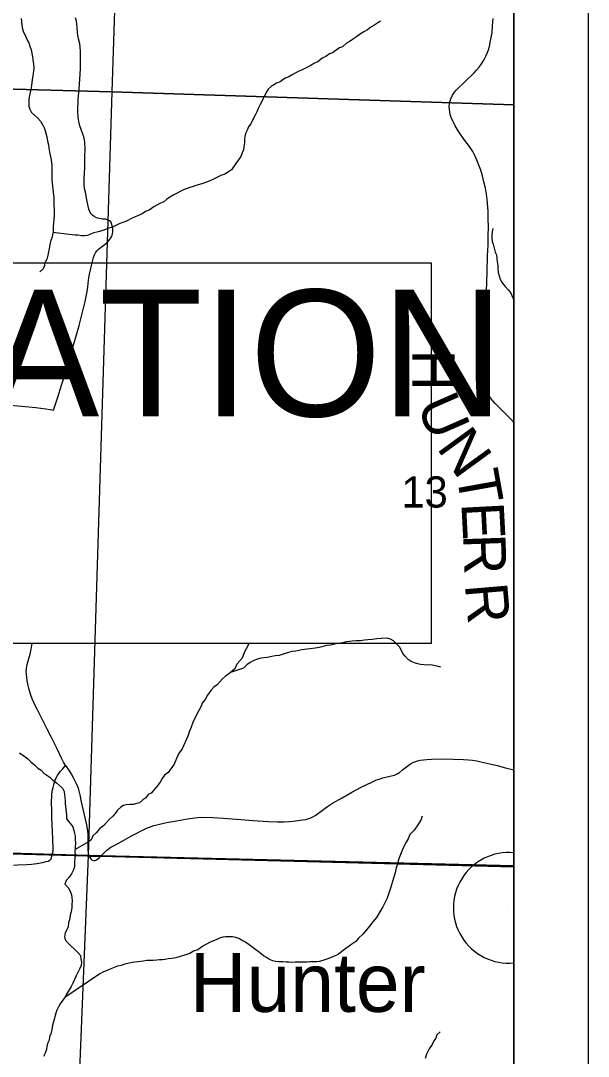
# Model space of a CAD drawing. Extents: x -7.9 to 76.1, y 0 to 22.
# Drawn here: x 8.238 to 9, y 17.882 to 19.274 of the extents above; entities that cross this region are included whole.
import ezdxf

# ---------------------------------------------------------------- set-up
doc = ezdxf.new("R2010")
doc.units = 0
for name, color, linetype in [('DV_X_Township_Line', 7, 'Continuous'), ('GM_X_Corporation_Text', 7, 'Continuous'), ('GM_X_County_Road', 7, 'Continuous'), ('GM_X_County_Road_Text', 7, 'Continuous'), ('GM_X_Minor_River', 7, 'Continuous'), ('GM_X_Section', 7, 'Continuous'), ('GM_X_Section_Text', 7, 'Continuous'), ('GM_X_Township_Road', 7, 'Continuous'), ('GM_X_Unincorporated_Location', 7, 'Continuous'), ('GM_X_Unincorporated_Text', 7, 'Continuous'), ('SC_Scratch1', 7, 'Continuous'), ('SH_Data', 7, 'Continuous'), ('SH_Text', 7, 'Continuous')]:
    doc.layers.add(name, color=color, linetype=linetype)

msp = doc.modelspace()

# ---------------------------------------------------------------- linework, layer by layer
at = {"layer": 'DV_X_Township_Line'}
msp.add_lwpolyline([(5.4916, 20.9), (5.4589, 19.5934), (5.4537, 19.3537), (5.4527, 19.3121), (5.4518, 19.2705), (5.4514, 19.2515), (5.451, 19.2324), (5.4237, 18.2356), (6.0503, 18.2178), (7.6352, 18.1705), (8.1733, 18.1556), (8.2754, 18.1527), (8.3264, 18.1514), (8.3292, 18.1513), (8.3352, 18.1512), (8.3434, 18.151), (8.9, 18.1366), (8.9, 18.1366)], dxfattribs=at)
at = {"layer": 'GM_X_Corporation_Text'}
msp.add_line((8.9, 18.0076), (8.9, 18.1558), dxfattribs=at)
msp.add_arc((8.8933, 18.0817), 0.0744, 84.8505, 275.1495, dxfattribs=at)
at = {"layer": 'GM_X_County_Road'}
msp.add_lwpolyline([(8.9, 18.7338), (8.8999, 18.7339), (8.8956, 18.7388), (8.8898, 18.7447), (8.8814, 18.7529), (8.8749, 18.7593), (8.8716, 18.763), (8.8687, 18.767), (8.8665, 18.7707), (8.8646, 18.7744), (8.8634, 18.7777), (8.8624, 18.7815), (8.8617, 18.7852), (8.8613, 18.7891), (8.8609, 18.796), (8.861, 18.8068), (8.8617, 18.8239), (8.8623, 18.8407), (8.8626, 18.8587), (8.8627, 18.8808), (8.863, 18.8956), (8.8633, 18.9096), (8.8637, 18.9229), (8.8641, 18.9362), (8.8647, 18.9576), (8.8654, 18.972), (8.8657, 18.9852), (8.866, 18.9959), (8.8657, 19.0077), (8.8655, 19.017), (8.8651, 19.0231), (8.864, 19.0335), (8.8631, 19.0406), (8.8619, 19.0484), (8.8599, 19.0572), (8.858, 19.0653), (8.8555, 19.0726), (8.8532, 19.0794), (8.8502, 19.0862), (8.8475, 19.0923), (8.8448, 19.0976), (8.8403, 19.1045), (8.8329, 19.1146), (8.8272, 19.1228), (8.8239, 19.128), (8.8214, 19.1323), (8.8188, 19.1371), (8.8165, 19.1422), (8.8147, 19.1474), (8.8139, 19.151), (8.8136, 19.1537), (8.8133, 19.1586), (8.8135, 19.1616), (8.8143, 19.1652), (8.8158, 19.1694), (8.8176, 19.1733), (8.8204, 19.1774), (8.8227, 19.1802), (8.8348, 19.192), (8.8467, 19.2035), (8.85, 19.207), (8.8533, 19.211), (8.8566, 19.2155), (8.859, 19.2193), (8.8607, 19.2224), (8.8623, 19.226), (8.8641, 19.2299), (8.866, 19.2345), (8.8673, 19.239), (8.8684, 19.2442), (8.8697, 19.2511), (8.8708, 19.2576), (8.8715, 19.2668), (8.8724, 19.2767)], dxfattribs=at)
at = {"layer": 'GM_X_Minor_River'}
for points in [[(8.2383, 19.2766), (8.2392, 19.2678), (8.2396, 19.2641), (8.2416, 19.258), (8.2447, 19.2524), (8.2466, 19.2475), (8.2486, 19.2437), (8.2502, 19.2392), (8.2517, 19.2346), (8.2538, 19.2252), (8.2542, 19.2214), (8.255, 19.2153), (8.2555, 19.2104), (8.2548, 19.2062), (8.2541, 19.199), (8.2534, 19.1944), (8.2527, 19.1906), (8.2524, 19.1864), (8.2513, 19.1811), (8.2506, 19.1773), (8.2495, 19.1731), (8.2489, 19.1682), (8.2485, 19.1636), (8.2486, 19.1587), (8.2502, 19.1545), (8.2525, 19.15), (8.261, 19.1425), (8.2644, 19.1384), (8.2679, 19.1324), (8.2699, 19.1286), (8.2715, 19.1226), (8.2727, 19.1176), (8.2739, 19.1116), (8.2751, 19.1067), (8.2755, 19.1021), (8.2764, 19.0968), (8.2784, 19.0889), (8.2792, 19.0832), (8.2796, 19.079), (8.2797, 19.0737), (8.2794, 19.0661), (8.2795, 19.0597), (8.2799, 19.0559), (8.2804, 19.051), (8.2808, 19.0472), (8.2816, 19.043), (8.2825, 19.0354), (8.2822, 19.0297), (8.2823, 19.0248), (8.2827, 19.021), (8.2828, 19.0161), (8.2828, 19.0123), (8.2821, 19.0066), (8.2815, 18.9971), (8.2812, 18.9899), (8.2798, 18.9819), (8.278, 18.9769), (8.2769, 18.9723), (8.2762, 18.9674), (8.2751, 18.9632), (8.2741, 18.9586), (8.273, 18.9533), (8.2704, 18.9483), (8.2697, 18.9445), (8.2679, 18.94), (8.2637, 18.9361)], [(8.721, 19.2728), (8.7173, 19.2708), (8.712, 19.2669), (8.7079, 19.265), (8.7037, 19.2615), (8.6985, 19.2588), (8.6943, 19.2561), (8.6887, 19.2518), (8.6846, 19.2491), (8.6804, 19.246), (8.6755, 19.2433), (8.6699, 19.2386), (8.6661, 19.2371), (8.6613, 19.234), (8.6564, 19.2305), (8.6526, 19.2289), (8.6477, 19.2254), (8.6428, 19.2231), (8.6368, 19.2184), (8.6323, 19.2165), (8.6263, 19.213), (8.615, 19.2071), (8.6105, 19.2052), (8.6063, 19.2032), (8.6022, 19.2009), (8.5977, 19.1981), (8.5928, 19.1962), (8.5864, 19.1915), (8.5815, 19.1896), (8.5777, 19.1876), (8.574, 19.1853), (8.5702, 19.1814), (8.5676, 19.1772), (8.5617, 19.165), (8.5595, 19.1608), (8.5569, 19.1554), (8.5551, 19.1509), (8.5525, 19.1466), (8.5488, 19.139), (8.547, 19.1348), (8.5436, 19.131), (8.5418, 19.1267), (8.5403, 19.1229), (8.5388, 19.118), (8.5385, 19.1142), (8.5382, 19.1096), (8.5375, 19.1043), (8.5368, 19.1001), (8.5353, 19.0959), (8.5335, 19.0913), (8.5302, 19.0867), (8.5268, 19.0818), (8.5209, 19.0733), (8.5156, 19.0695), (8.5118, 19.0675), (8.5066, 19.0655), (8.496, 19.0601), (8.4907, 19.0581), (8.4824, 19.0549), (8.4779, 19.0534), (8.473, 19.0521), (8.4692, 19.0506), (8.4647, 19.0494), (8.4564, 19.0462), (8.4519, 19.0439), (8.4477, 19.0419), (8.4436, 19.0396), (8.4391, 19.0369), (8.4342, 19.0338), (8.4301, 19.0303), (8.4248, 19.0279), (8.4165, 19.0233), (8.4105, 19.019), (8.4056, 19.017), (8.4011, 19.0143), (8.3958, 19.012), (8.3917, 19.01), (8.3864, 19.0077), (8.38, 19.0042), (8.3751, 19.0026), (8.3709, 19.001), (8.3657, 18.9983), (8.36, 18.9959), (8.3558, 18.9947), (8.3517, 18.9931), (8.3479, 18.9916), (8.3438, 18.9904), (8.34, 18.9895), (8.3362, 18.9884), (8.3317, 18.9868), (8.3275, 18.9848), (8.3234, 18.9844), (8.3196, 18.9843), (8.3146, 18.9854), (8.3109, 18.9853), (8.3071, 18.9857), (8.3029, 18.9864), (8.2811, 18.9892)], [(8.8719, 18.9944), (8.8708, 18.9898), (8.8705, 18.986), (8.8706, 18.9819), (8.871, 18.9769), (8.8722, 18.9732), (8.875, 18.9626), (8.8766, 18.9588), (8.8774, 18.9539), (8.8778, 18.9497), (8.8786, 18.9448), (8.8787, 18.9406), (8.8792, 18.9353), (8.8804, 18.9308), (8.8815, 18.9262), (8.8843, 18.9213), (8.8885, 18.9164), (8.8924, 18.9119), (8.8954, 18.9082), (8.8974, 18.9044), (8.899, 18.9003), (8.9, 18.8979)], [(8.5443, 18.4369), (8.5421, 18.4317), (8.5384, 18.4256), (8.5351, 18.4172), (8.528, 18.4091), (8.5254, 18.4026), (8.5217, 18.3995), (8.5175, 18.3961), (8.5127, 18.3929), (8.5089, 18.3895), (8.5018, 18.3814), (8.4973, 18.3783), (8.4932, 18.3737), (8.4887, 18.3676), (8.4854, 18.3614), (8.4817, 18.3568), (8.4802, 18.3526), (8.4769, 18.3469), (8.4713, 18.3354), (8.4688, 18.3308), (8.4666, 18.3243), (8.4644, 18.319), (8.4622, 18.3125), (8.4548, 18.2953), (8.4496, 18.2884), (8.447, 18.2823), (8.4437, 18.2747), (8.4359, 18.2635), (8.4307, 18.26), (8.4277, 18.2554), (8.4251, 18.2505), (8.4206, 18.2447), (8.4128, 18.2359)], [(8.8022, 18.405), (8.7969, 18.4064), (8.7927, 18.4071), (8.7881, 18.4082), (8.7836, 18.4078), (8.7794, 18.4081), (8.7748, 18.4088), (8.771, 18.4095), (8.7665, 18.4109), (8.7623, 18.4128), (8.7581, 18.4154), (8.7542, 18.4199), (8.7511, 18.4236), (8.7488, 18.4285), (8.7464, 18.4323), (8.743, 18.436), (8.7384, 18.4405), (8.7346, 18.4428), (8.73, 18.4438), (8.722, 18.4437), (8.716, 18.4433), (8.7099, 18.442), (8.7039, 18.4416), (8.6993, 18.4411), (8.694, 18.4403), (8.6883, 18.4402), (8.683, 18.4398), (8.6792, 18.4397), (8.6747, 18.4389), (8.6698, 18.4377), (8.6652, 18.4369), (8.6615, 18.4364), (8.6539, 18.4348), (8.6486, 18.434), (8.6422, 18.4324), (8.6384, 18.4315), (8.6331, 18.4307), (8.6267, 18.4295), (8.6225, 18.429), (8.6153, 18.4282), (8.6111, 18.4274), (8.6074, 18.4265), (8.6021, 18.4261), (8.596, 18.4241), (8.5915, 18.4229), (8.5847, 18.4209), (8.5794, 18.4201), (8.5749, 18.4193), (8.5688, 18.418), (8.5601, 18.4171), (8.5556, 18.4159), (8.551, 18.414), (8.5461, 18.4113), (8.5416, 18.4082), (8.5368, 18.4039), (8.5195, 18.3977)], [(8.2361, 18.29), (8.2419, 18.2859), (8.2472, 18.2818), (8.2514, 18.278), (8.2561, 18.2736), (8.2607, 18.2694), (8.2653, 18.2665), (8.2687, 18.2627), (8.2729, 18.2601), (8.2768, 18.2571), (8.281, 18.2534), (8.286, 18.2497), (8.2898, 18.2459), (8.294, 18.2426), (8.296, 18.238), (8.2968, 18.2335), (8.2972, 18.2297), (8.2973, 18.2255), (8.2977, 18.2217), (8.2978, 18.2179), (8.2982, 18.2141), (8.2991, 18.2062), (8.2995, 18.2016), (8.3018, 18.1979), (8.3053, 18.1941), (8.308, 18.1904), (8.3092, 18.1858), (8.31, 18.1817), (8.3108, 18.1779), (8.3109, 18.1737), (8.3113, 18.1684), (8.311, 18.1631), (8.3107, 18.157), (8.3108, 18.1528), (8.3105, 18.1479), (8.3102, 18.1433), (8.3099, 18.1372), (8.3088, 18.1327), (8.3058, 18.1273), (8.3029, 18.1231), (8.2987, 18.1185), (8.2969, 18.1135), (8.3015, 18.109), (8.3043, 18.1041), (8.3062, 18.0992), (8.3063, 18.0954), (8.3067, 18.0909), (8.3064, 18.0859), (8.3065, 18.0821), (8.3054, 18.0764), (8.3043, 18.0718), (8.3033, 18.0657), (8.3022, 18.0619), (8.3015, 18.0562), (8.2997, 18.052), (8.2974, 18.0482), (8.2964, 18.0429), (8.2976, 18.0387), (8.301, 18.0346), (8.3145, 18.0215), (8.3179, 18.0177), (8.3184, 18.0132), (8.3196, 18.0086), (8.3189, 18.0041), (8.3174, 18.0002), (8.3148, 17.9957), (8.3123, 17.9903), (8.3078, 17.9804), (8.3056, 17.9762), (8.303, 17.9716), (8.3001, 17.967), (8.2971, 17.9612)], [(8.4128, 18.2359), (8.409, 18.2339), (8.4057, 18.2293), (8.4019, 18.227), (8.3974, 18.2227), (8.3936, 18.2219), (8.3887, 18.2207), (8.3849, 18.2207), (8.3796, 18.2202), (8.3759, 18.219), (8.3721, 18.2171), (8.368, 18.2128), (8.3646, 18.2086), (8.3613, 18.2048), (8.3564, 18.2005), (8.3493, 18.1925), (8.3441, 18.1882), (8.3392, 18.1824), (8.3347, 18.1782), (8.3325, 18.1729), (8.3287, 18.1705), (8.3109, 18.1601)], [(8.7769, 18.2049), (8.775, 18.1996), (8.7713, 18.1934), (8.7661, 18.1861), (8.7605, 18.18), (8.7579, 18.1746), (8.7553, 18.1697), (8.7513, 18.1624), (8.7461, 18.149), (8.7447, 18.1448), (8.744, 18.141), (8.7422, 18.1353), (8.7407, 18.1288), (8.7386, 18.1216), (8.7346, 18.1082), (8.7327, 18.1029), (8.7298, 18.0945), (8.7272, 18.0891), (8.7239, 18.083), (8.7202, 18.0765), (8.7154, 18.0688), (8.7105, 18.0627), (8.7061, 18.0569), (8.702, 18.0523), (8.6971, 18.0462), (8.6915, 18.0408), (8.6878, 18.0366), (8.6825, 18.0327), (8.6788, 18.03), (8.6746, 18.0269), (8.6634, 18.0187), (8.6588, 18.0168), (8.654, 18.0144), (8.6475, 18.0125), (8.6434, 18.0109), (8.6388, 18.0097), (8.6351, 18.0092), (8.626, 18.0091), (8.6222, 18.0087), (8.618, 18.0086), (8.6142, 18.0086), (8.61, 18.0089), (8.6062, 18.0088), (8.6021, 18.0084), (8.5979, 18.0087), (8.5941, 18.0087), (8.5899, 18.009), (8.5846, 18.0093), (8.5801, 18.0096), (8.5763, 18.0103), (8.5721, 18.0122), (8.5679, 18.0148), (8.564, 18.017), (8.5583, 18.0218), (8.5518, 18.0267), (8.5464, 18.0308), (8.5395, 18.0356), (8.5353, 18.0378), (8.5307, 18.0404), (8.5269, 18.0419), (8.5224, 18.0426), (8.5174, 18.0429), (8.5129, 18.0428), (8.5091, 18.0424), (8.5049, 18.0408), (8.5004, 18.0389), (8.4967, 18.0373), (8.4914, 18.035), (8.4823, 18.0303), (8.4756, 18.0252), (8.4699, 18.0233), (8.465, 18.0205), (8.4609, 18.019), (8.4564, 18.0178), (8.4518, 18.0162), (8.4462, 18.0146), (8.4409, 18.0137), (8.4359, 18.0133), (8.4318, 18.0125), (8.428, 18.012), (8.4242, 18.012), (8.4204, 18.0116), (8.4159, 18.0111), (8.4121, 18.0111), (8.4068, 18.011), (8.4026, 18.0102), (8.3875, 18.0084), (8.3776, 18.006), (8.3727, 18.0044), (8.3678, 18.0032), (8.3633, 18.0016), (8.3588, 17.9997), (8.3546, 17.9981), (8.349, 17.9957), (8.3441, 17.993), (8.2971, 17.9612)], [(8.2971, 17.9612), (8.2938, 17.957), (8.2908, 17.9528), (8.2886, 17.9486), (8.2863, 17.944), (8.2849, 17.9402), (8.282, 17.9287), (8.2806, 17.9242), (8.2795, 17.9184), (8.2781, 17.9124), (8.2766, 17.9082), (8.2759, 17.904), (8.2744, 17.9001), (8.273, 17.896), (8.2723, 17.8914), (8.2705, 17.8864), (8.2682, 17.8818)], [(8.8009, 17.9151), (8.7968, 17.9109), (8.7953, 17.9067), (8.7924, 17.9028), (8.7905, 17.8979), (8.7864, 17.8921), (8.7827, 17.8852), (8.7809, 17.8791)]]:
    msp.add_lwpolyline(points, dxfattribs=at)
at = {"layer": 'GM_X_Section'}
for points in [[(7.3774, 20.223), (8.3939, 20.1994), (8.3601, 19.1779), (7.3421, 19.2056)], [(7.3421, 19.2056), (8.3601, 19.1779), (8.3283, 18.1522), (7.3083, 18.1826)], [(7.3083, 18.1826), (8.3283, 18.1522), (8.2894, 17.1874), (7.2713, 17.2194)]]:
    msp.add_lwpolyline(points, close=True, dxfattribs=at)
at = {"layer": 'GM_X_Township_Road'}
for points in [[(8.2818, 18.7502), (8.2846, 18.7583), (8.2877, 18.7676), (8.2928, 18.7838), (8.2982, 18.8008), (8.3013, 18.8119), (8.3048, 18.8242), (8.3082, 18.8361), (8.3125, 18.8513), (8.3161, 18.8641), (8.3193, 18.8764), (8.3242, 18.8964), (8.3272, 18.9097), (8.3281, 18.9154), (8.3286, 18.9208), (8.3293, 18.928), (8.3302, 18.933), (8.3314, 18.9386), (8.3329, 18.9447), (8.3356, 18.9553), (8.3369, 18.9591), (8.3382, 18.9616), (8.3402, 18.9643), (8.3423, 18.9665), (8.3495, 18.9718), (8.3538, 18.9754), (8.3567, 18.9788), (8.3589, 18.9819), (8.3597, 18.9834), (8.3605, 18.9853), (8.3611, 18.9872), (8.3614, 18.9897), (8.3613, 18.994), (8.3607, 18.9978), (8.3599, 19.0009), (8.3587, 19.0033), (8.357, 19.0048), (8.3543, 19.006), (8.3517, 19.0067), (8.3471, 19.0071), (8.343, 19.0077), (8.3397, 19.0088), (8.3364, 19.0103), (8.3343, 19.0122), (8.3324, 19.0142), (8.3311, 19.016), (8.3301, 19.0181), (8.3292, 19.0205), (8.3283, 19.0243), (8.3265, 19.0331), (8.3246, 19.043), (8.3236, 19.0482), (8.323, 19.0526), (8.3228, 19.0584), (8.3229, 19.062), (8.3235, 19.0685), (8.3239, 19.0763), (8.3241, 19.0906), (8.3242, 19.1015), (8.324, 19.1104), (8.3235, 19.1133), (8.3224, 19.1175), (8.3213, 19.1209), (8.3189, 19.1274), (8.3173, 19.1323), (8.3159, 19.1382), (8.315, 19.1437), (8.3145, 19.1526), (8.3149, 19.1676), (8.3161, 19.1821), (8.3172, 19.1952), (8.3179, 19.2091), (8.3182, 19.2187), (8.3183, 19.2259), (8.318, 19.2322), (8.3175, 19.2385), (8.317, 19.2423), (8.3155, 19.249), (8.3142, 19.2571), (8.3135, 19.2649), (8.313, 19.2693), (8.3126, 19.2728), (8.3115, 19.2772)], [(8.2243, 18.7568), (8.2388, 18.7558), (8.2583, 18.754), (8.2715, 18.7522), (8.2775, 18.7511), (8.2818, 18.7502)], [(8.2981, 18.2729), (8.2954, 18.2773), (8.2925, 18.2827), (8.2867, 18.2952), (8.2788, 18.3114), (8.2733, 18.3217), (8.2674, 18.3334), (8.2601, 18.3484), (8.2578, 18.3528), (8.2555, 18.3576), (8.2534, 18.3625), (8.2516, 18.3674), (8.2492, 18.3748), (8.2473, 18.3825), (8.2464, 18.3867), (8.2458, 18.391), (8.2454, 18.3955), (8.2453, 18.3994), (8.2457, 18.4032), (8.2466, 18.4085), (8.2481, 18.415), (8.2503, 18.4226), (8.2518, 18.4292), (8.2528, 18.4348), (8.2531, 18.4369)], [(8.3528, 18.1585), (8.3536, 18.1591), (8.3552, 18.1606), (8.3587, 18.1631), (8.3659, 18.167), (8.3773, 18.1732), (8.3867, 18.1783), (8.3946, 18.1825), (8.3988, 18.1848), (8.4026, 18.1866), (8.4069, 18.1886), (8.4108, 18.1901), (8.4164, 18.1921), (8.4205, 18.1934), (8.4337, 18.1962), (8.4471, 18.1984), (8.4618, 18.2013), (8.4717, 18.2027), (8.48, 18.2035), (8.4961, 18.2032), (8.51, 18.2022), (8.5334, 18.2003), (8.5495, 18.1991), (8.5706, 18.1976), (8.5826, 18.1972), (8.5916, 18.1974), (8.5984, 18.1978), (8.6035, 18.1982), (8.6161, 18.1997), (8.6202, 18.2004), (8.6233, 18.2012), (8.6272, 18.2025), (8.6301, 18.2038), (8.6341, 18.2063), (8.6377, 18.2088), (8.6465, 18.2156), (8.6498, 18.2179), (8.6565, 18.2223), (8.6694, 18.2296), (8.6833, 18.2374), (8.6949, 18.2437), (8.7095, 18.2507), (8.7147, 18.2531), (8.717, 18.254), (8.7204, 18.2552), (8.7242, 18.2563), (8.7374, 18.2593), (8.7399, 18.2601), (8.7415, 18.2608), (8.7441, 18.2621), (8.7464, 18.2636), (8.7507, 18.2669), (8.7614, 18.275), (8.7642, 18.2768), (8.767, 18.278), (8.7705, 18.2791), (8.7743, 18.28), (8.7785, 18.2806), (8.7832, 18.281), (8.7895, 18.2813), (8.8025, 18.2818), (8.8191, 18.2814), (8.8325, 18.281), (8.8391, 18.2807), (8.8443, 18.2802), (8.8503, 18.279), (8.8555, 18.2779), (8.8678, 18.275), (8.8775, 18.2727), (8.8888, 18.27), (8.9, 18.2673)], [(8.2816, 18.1614), (8.2809, 18.1744), (8.2804, 18.1843), (8.2796, 18.2032), (8.2794, 18.2127), (8.2791, 18.2229), (8.2795, 18.2333), (8.2802, 18.2385), (8.2812, 18.2434), (8.2827, 18.2489), (8.2842, 18.2533), (8.2856, 18.2564), (8.2873, 18.2597), (8.2889, 18.2623), (8.2908, 18.2647), (8.2939, 18.2682), (8.2981, 18.2729), (8.303, 18.2659), (8.3061, 18.261), (8.3084, 18.2569), (8.3107, 18.2525), (8.3133, 18.2468), (8.3148, 18.2423), (8.317, 18.2335), (8.3192, 18.2239), (8.3214, 18.2142), (8.326, 18.1932), (8.3276, 18.1847), (8.3279, 18.1804), (8.3281, 18.1598)], [(8.2281, 18.1392), (8.234, 18.1393), (8.2462, 18.1397), (8.2524, 18.1402), (8.2593, 18.1412), (8.267, 18.1426), (8.2722, 18.1439), (8.2747, 18.1446), (8.2768, 18.1458), (8.2785, 18.1477), (8.2797, 18.1506), (8.2807, 18.155), (8.2812, 18.1584), (8.2816, 18.1614)], [(8.3281, 18.1598), (8.3286, 18.1556), (8.3295, 18.152), (8.3306, 18.1494), (8.3322, 18.1469), (8.3338, 18.1456), (8.3358, 18.1451), (8.3379, 18.1453), (8.3397, 18.1461), (8.3432, 18.149), (8.3507, 18.1564), (8.3528, 18.1585)]]:
    msp.add_lwpolyline(points, dxfattribs=at)
at = {"layer": 'GM_X_Unincorporated_Location'}
msp.add_line((8.8933, 18.0817), (8.8933, 18.0817), dxfattribs=at)
at = {"layer": 'SC_Scratch1'}
for points in [[(8.9, 19.1606), (8.9, 20.1803), (8.3939, 20.1994), (8.3601, 19.1779)], [(8.9, 18.1379), (8.9, 19.1606), (8.3601, 19.1779), (8.3283, 18.1522)], [(8.9, 17.1682), (8.9, 18.1379), (8.3283, 18.1522), (8.2894, 17.1874)]]:
    msp.add_lwpolyline(points, close=True, dxfattribs=at)
at = {"layer": 'SH_Data'}
for p, q in [((9, 21), (9, 14)), ((8.9, 20.9), (8.9, 14.1))]:
    msp.add_line(p, q, dxfattribs=at)
at = {"layer": 'SH_Text'}
msp.add_lwpolyline([(6.5481, 18.9482), (8.7892, 18.9482), (8.7892, 18.4369), (6.5481, 18.4369)], close=True, dxfattribs=at)

# ---------------------------------------------------------------- texts
at = {"layer": 'GM_X_County_Road_Text'}
for s, rotation, p in [('H', 269.7851, (8.7638, 18.8316)), ('U', 293.6687, (8.7688, 18.7569)), ('N', 306.1067, (8.7954, 18.6996)), ('T', 280.1718, (8.8223, 18.6654)), ('E', 273.0056, (8.8295, 18.6254)), ('R', 272.0847, (8.8318, 18.5832)), ('R', 274.8511, (8.8342, 18.516))]:
    msp.add_text(s, height=0.0568, rotation=rotation, dxfattribs=at).set_placement(p)
at = {"layer": 'GM_X_Section_Text'}
msp.add_text('13', height=0.04186, rotation=0, dxfattribs=at).set_placement((8.749, 18.6195))
at = {"layer": 'GM_X_Unincorporated_Text'}
msp.add_text('Hunter', height=0.07898, rotation=0, dxfattribs=at).set_placement((8.4648, 17.9419))
at = {"layer": 'SH_Text'}
msp.add_text('PROJECT LOCATION', height=0.17, dxfattribs=at).set_placement((6.6002, 18.742))

doc.saveas('drawing.dxf')
